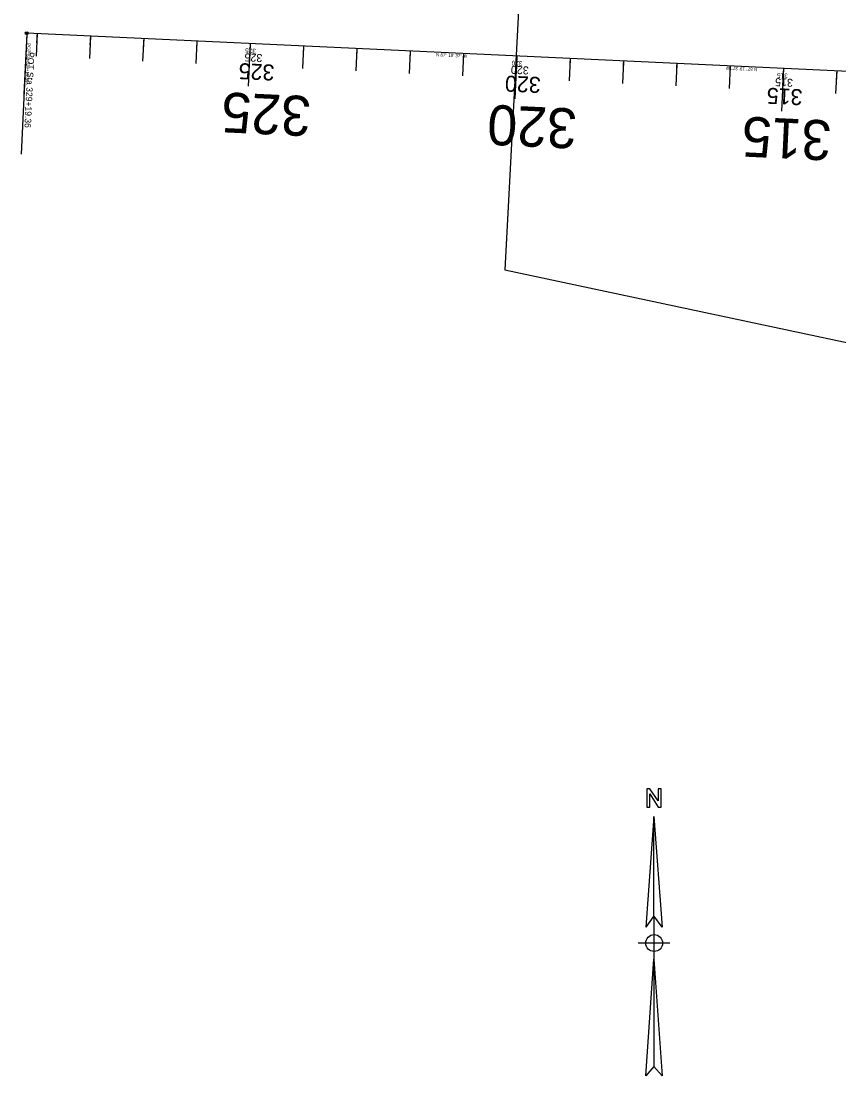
# Model space of a CAD drawing. Extents: x 2358865 to 2362945, y 393485 to 404880.
# Drawn here: x 2359058 to 2360591, y 400444 to 402421 of the extents above; entities that cross this region are included whole.
import ezdxf

# ---------------------------------------------------------------- set-up
doc = ezdxf.new("R2010")
doc.units = 0
for name, color, linetype in [('CL', 7, 'Continuous'), ('Level 10', 7, 'Continuous'), ('Level 21', 7, 'Continuous'), ('Level 25', 7, 'Continuous'), ('Level 28', 7, 'Continuous'), ('Level 30', 7, 'Continuous'), ('Level 33', 7, 'Continuous'), ('Level 39', 7, 'Continuous'), ('Level 41', 7, 'Continuous'), ('Level 63', 7, 'Continuous')]:
    doc.layers.add(name, color=color, linetype=linetype)

msp = doc.modelspace()

# ---------------------------------------------------------------- linework, layer by layer
at = {"layer": 'CL'}
msp.add_line((2360672.4, 402323.8), (2359068.7, 402398.7), dxfattribs=at)
at = {"layer": 'Level 10'}
for p, q in [((2360244.1, 400930.3), (2360228.5, 400723.1)), ((2360244.1, 400930.3), (2360259.7, 400723.1)), ((2360244.1, 400744.4), (2360244.1, 400930.3)), ((2360244.1, 400744.4), (2360228.5, 400723.1)), ((2360244.1, 400744.4), (2360244.1, 400662.8)), ((2360259.7, 400723.1), (2360244.1, 400744.4)), ((2360273.9, 400693.1), (2360214.6, 400693.1)), ((2360228.5, 400444.1), (2360244.1, 400662.8)), ((2360244.1, 400662.8), (2360259.7, 400444.1)), ((2360244.1, 400662.8), (2360244.1, 400461.6)), ((2360244.1, 400461.6), (2360228.5, 400444.1)), ((2360259.7, 400444.1), (2360244.1, 400461.6))]:
    msp.add_line(p, q, dxfattribs=at)
msp.add_lwpolyline([(2360230.7, 400982.5), (2360230.7, 400947.8), (2360236.3, 400947.8), (2360236.3, 400969.1), (2360236.3, 400972.8), (2360251.9, 400947.8), (2360257.5, 400947.8), (2360257.5, 400982.5), (2360251.9, 400982.5), (2360251.9, 400961.3), (2360251.9, 400959.4), (2360236.3, 400982.5), (2360230.7, 400982.5)], dxfattribs=at)
msp.add_circle((2360244.3, 400693.1), 15.8, dxfattribs=at)
at = {"layer": 'Level 25'}
for p, q in [((2359088.1, 402397.8), (2359087.8, 402392.8)), ((2359188, 402393.2), (2359187.7, 402388.2)), ((2359287.9, 402388.5), (2359287.6, 402383.5)), ((2359387.7, 402383.8), (2359387.5, 402378.8)), ((2359487.6, 402379.2), (2359487.3, 402371.2)), ((2359587.5, 402374.5), (2359587.3, 402369.5)), ((2359687.4, 402369.8), (2359687.2, 402364.8)), ((2359787.3, 402365.2), (2359787.1, 402360.2)), ((2359887.2, 402360.5), (2359887, 402355.5)), ((2359987.1, 402355.8), (2359986.7, 402347.9)), ((2360087, 402351.2), (2360086.7, 402346.2)), ((2360186.9, 402346.5), (2360186.6, 402341.5)), ((2360286.8, 402341.9), (2360286.5, 402336.9)), ((2360386.7, 402337.2), (2360386.4, 402332.2)), ((2360486.5, 402332.5), (2360486.2, 402324.5)), ((2360586.4, 402327.9), (2360586.2, 402322.9))]:
    msp.add_line(p, q, dxfattribs=at)
at = {"layer": 'Level 28'}
msp.add_line((2359068.7, 402397.5), (2359063.4, 402284.2), dxfattribs=at)
msp.add_circle((2359068.7, 402398.7), 1.25, dxfattribs=at)
at = {"layer": 'Level 30'}
for p, q in [((2359088.1, 402397.8), (2359087.7, 402389.3)), ((2359188, 402393.2), (2359187.6, 402384.7)), ((2359287.9, 402388.5), (2359287.5, 402380)), ((2359387.7, 402383.8), (2359387.3, 402375.3)), ((2359487.6, 402379.2), (2359486.9, 402363.2)), ((2359587.5, 402374.5), (2359587.1, 402366)), ((2359687.4, 402369.8), (2359687, 402361.3)), ((2359787.3, 402365.2), (2359786.9, 402356.7)), ((2359887.2, 402360.5), (2359886.8, 402352)), ((2359987.1, 402355.8), (2359986.3, 402339.9)), ((2360087, 402351.2), (2360086.6, 402342.7)), ((2360186.9, 402346.5), (2360186.5, 402338)), ((2360286.8, 402341.9), (2360286.4, 402333.4)), ((2360386.7, 402337.2), (2360386.3, 402328.7)), ((2360486.5, 402332.5), (2360485.8, 402316.5)), ((2360586.4, 402327.9), (2360586, 402319.4))]:
    msp.add_line(p, q, dxfattribs=at)
at = {"layer": 'Level 33'}
msp.add_line((2359068.6, 402396), (2359058.1, 402172.1), dxfattribs=at)
msp.add_circle((2359068.7, 402398.7), 2.7, dxfattribs=at)
at = {"layer": 'Level 39'}
for p, q in [((2359088.1, 402397.8), (2359087.3, 402380.8)), ((2359188, 402393.2), (2359187.2, 402376.2)), ((2359287.9, 402388.5), (2359287.1, 402371.5)), ((2359387.7, 402383.8), (2359386.9, 402366.8)), ((2359487.6, 402379.2), (2359486.1, 402347.2)), ((2359587.5, 402374.5), (2359586.7, 402357.5)), ((2359687.4, 402369.8), (2359686.6, 402352.9)), ((2359787.3, 402365.2), (2359786.5, 402348.2)), ((2359887.2, 402360.5), (2359886.4, 402343.5)), ((2359987.1, 402355.8), (2359985.6, 402323.9)), ((2360087, 402351.2), (2360086.2, 402334.2)), ((2360186.9, 402346.5), (2360186.1, 402329.5)), ((2360286.8, 402341.9), (2360286, 402324.9)), ((2360386.7, 402337.2), (2360385.9, 402320.2)), ((2360486.5, 402332.5), (2360485.1, 402300.6)), ((2360586.4, 402327.9), (2360585.6, 402310.9))]:
    msp.add_line(p, q, dxfattribs=at)
at = {"layer": 'Level 41'}
for p, q in [((2359088.1, 402397.8), (2359086.1, 402355.9)), ((2359188, 402393.2), (2359186, 402351.2)), ((2359287.9, 402388.5), (2359285.9, 402346.5)), ((2359387.7, 402383.8), (2359385.8, 402341.9)), ((2359487.6, 402379.2), (2359483.9, 402299.2)), ((2359587.5, 402374.5), (2359585.6, 402332.5)), ((2359687.4, 402369.8), (2359685.5, 402327.9)), ((2359787.3, 402365.2), (2359785.3, 402323.2)), ((2359887.2, 402360.5), (2359885.2, 402318.6)), ((2359987.1, 402355.8), (2359983.4, 402275.9)), ((2360087, 402351.2), (2360085, 402309.2)), ((2360186.9, 402346.5), (2360184.9, 402304.6)), ((2360286.8, 402341.9), (2360284.8, 402299.9)), ((2360386.7, 402337.2), (2360384.7, 402295.2)), ((2360486.5, 402332.5), (2360482.8, 402252.6)), ((2360586.4, 402327.9), (2360584.5, 402285.9))]:
    msp.add_line(p, q, dxfattribs=at)
at = {"layer": 'Level 63'}
msp.add_lwpolyline([(2359964.7, 401954.9), (2361163.4, 401700.4), (2361426.4, 402053.5), (2361426.4, 402053.5), (2361515.9, 402173.8), (2361644.3, 402346.2), (2361509.4, 402444.8), (2360042.1, 402756.3), (2359995.2, 402535.3), (2359995.2, 402535.3)], close=True, dxfattribs=at)

# ---------------------------------------------------------------- texts
at = {"layer": 'Level 21'}
for rotation, p in [(357.327, (2359835.6, 402355.4)), (177.327, (2360437.6, 402333.4))]:
    msp.add_text('N 87%%d 19\' 37" W', height=6, rotation=rotation, dxfattribs=at).set_placement(p)
at = {"layer": 'Level 25'}
for s, p in [('325', (2359498.3, 402369.4)), ('320', (2359997.7, 402346.1)), ('315', (2360495, 402322.9))]:
    msp.add_text(s, height=8.75, rotation=177.327, dxfattribs=at).set_placement(p)
at = {"layer": 'Level 28'}
msp.add_text('POT Sta 329+19.36', height=6, rotation=267.327, dxfattribs=at).set_placement((2359069.9, 402379.9))
at = {"layer": 'Level 30'}
for s, p in [('325', (2359510.6, 402359.4)), ('320', (2360009.8, 402336.1)), ('315', (2360504.8, 402313))]:
    msp.add_text(s, height=15, rotation=177.327, dxfattribs=at).set_placement(p)
at = {"layer": 'Level 33'}
msp.add_text('POT Sta 329+19.36', height=12, rotation=267.327, dxfattribs=at).set_placement((2359071.1, 402363.6))
at = {"layer": 'Level 39'}
for s, p in [('325', (2359533.5, 402339.6)), ('320', (2360032.5, 402316.3)), ('315', (2360523, 402293.4))]:
    msp.add_text(s, height=30, rotation=177.327, dxfattribs=at).set_placement(p)
at = {"layer": 'Level 41'}
for s, p in [('325', (2359602.7, 402280.2)), ('320', (2360101, 402256.9)), ('315', (2360577.9, 402234.7))]:
    msp.add_text(s, height=75, rotation=177.327, dxfattribs=at).set_placement(p)

doc.saveas('drawing.dxf')
